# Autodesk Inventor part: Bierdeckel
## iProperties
Created: 2008-08
Part Number: Bierdeckel
Document SubType Name: Modeling
Designer: adscro24
Density: 1 g/cm^3
Author: adscro24
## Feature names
1. Umdrehung1 [Revolution]
2. Extrusion1
3. Extrusion2
4. Extrusion3
5. Extrusion4
6. Extrusion5
7. Extrusion6
8. Extrusion7
9. Extrusion8
